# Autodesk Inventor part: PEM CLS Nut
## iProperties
Author: John A. Hunter
Shininess: 64.0
Angle Display Precision: 2
Document Length Units: 11272
Document Angle Units: 11286
Document Time Units: 11279
Document Mass Units: 11290
Document Length Units Precision: 3
Document Angle Units Precision: 2
Compacted: True
PropertySet Name: _Private Model Information
Created: 2002-08
Part Number: PEM CLS Nut
Material: Stainless Steel, 440C
Description: CLS-632-2
Document SubType Name: Modeling
Designer: John A. Hunter
Control State: 0
Master: False
Checked Out: False
PropertySet Name: Design Tracking Control
Density: 0.0
Volumn: 0.0
Area: 0.0
PropertySet Name: Model Information
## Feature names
1. Extrusion1
2. Extrusion2
3. Hole1
